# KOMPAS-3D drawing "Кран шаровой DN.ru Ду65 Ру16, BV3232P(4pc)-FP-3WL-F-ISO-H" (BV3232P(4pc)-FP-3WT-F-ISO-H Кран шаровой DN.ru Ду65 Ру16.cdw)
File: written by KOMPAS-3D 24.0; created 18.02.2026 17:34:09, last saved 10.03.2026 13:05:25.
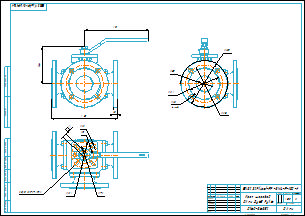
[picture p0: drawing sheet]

Document properties: Автор: R2D2; Форматы листов документа: A2; Полное имя файла: ..\..\BV3232P(4pc)-FP-3WL-F-ISO-H Кран шаровой DN.ru Ду15-100 Ру16\DN65\BV3232P(4pc)-FP-3WL-F-ISO-H Кран шаровой DN.ru Ду65 Ру16.cdw; Масса: 26.5; Наименование: Кран шаровой DN.ru Ду65 Ру16; Количество листов документа: 1; Примечание: D160-36361

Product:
- Part/product: Кран шаровой DN.ru Ду65 Ру16  | designation BV3232P(4pc)-FP-3WL-F-ISO-H
    Масса: 26.5
    Раздел спецификации: Прочие изделия
    Форматы листов документа: A2
    Примечание: D160-36361

Views: Проекционный вид 2
Referenced files in E:\Работа\Зайцев\BV3232P(4pc)-FP-3WL-F-ISO-H Кран шаровой DN.ru Ду15-100 Ру16\DN65\: BV3232P(4pc)-FP-3WL-F-ISO-H Кран шаровой DN.ru Ду65 Ру16.m3d
Referenced files in E:\Работа\Зайцев\Для компаса\: чертеж DN.ru А3.cdt
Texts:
  BV3232P(4pc)-FP-3WL-F-ISO-H
  чертеж DN.ru А3.cdt
  Кран шаровой
  DN.ru Ду65 Ру16
  Кран шаровой DN.ru Ду65 Ру16
  BV3232P(4pc)-FP-3WL-F-ISO-H Кран шаровой DN.ru Ду65 Ру16
Dimensions and other numbers on the sheet: 0; 3; 4; 185; 145; 122; 18; 4 отв.; 65; 1:2; 1; 2; 26,5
